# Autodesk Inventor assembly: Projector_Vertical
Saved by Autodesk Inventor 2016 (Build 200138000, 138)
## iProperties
Created: 2015-11
Part Number: Projector_Vertical
Document SubType Name: Assembly
Designer: John
Author: John
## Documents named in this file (3)
- D:\3D Printer Designs\John Ledden Designs\DLP Printer\V0-4\Projector_Vertical.iam
- D:\3D Printer Designs\John Ledden Designs\DLP Printer\V0-4\Acer_Projector.ipt
- D:\3D Printer Designs\John Ledden Designs\DLP Printer\V0-4\Frame_ProjectorMount.ipt
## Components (2 placed, 2 different names)
1. Acer_Projector_1010
2. Frame_ProjectorMount_1011
